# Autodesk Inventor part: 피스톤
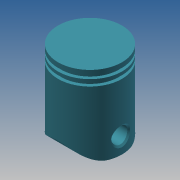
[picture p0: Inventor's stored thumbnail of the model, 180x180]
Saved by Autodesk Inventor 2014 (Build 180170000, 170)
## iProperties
Created: 2017-05
Part Number: 피스톤
Material: 알루미늄 6061
Document SubType Name: Modeling
Designer: mduedu
Density: 2.71 g/cm^3
Mass: 87.6985 g
Surface Area: 150.47 cm^2
Volume: 32.3611 cm^3
Appearance: 커뎃 파란색
Author: mduedu
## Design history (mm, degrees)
sketch "스케치1"
  geometry: L1 (0, 0)-(20, 0); L2 (20, -50)-(15, -50); L3 (15, -50)-(15, -5); L4 (15, -5)-(0, -5); L5 (0, -5)-(0, 0); L6 (20, -3)-(18, -3); L7 (18, -3)-(18, -5); L8 (18, -5)-(20, -5); L9 (20, -7)-(18, -7); L10 (18, -7)-(18, -9); L11 (18, -9)-(20, -9); L12 (20, 0)-(20, -3); L13 (20, -5)-(20, -7); L14 (20, -9)-(20, -50); L15 (0, -60)-(0, 10) reference
  constraints: 28 end point, 10 parallel, 5 perpendicular, 4 collinear, 3 horizontal
  dimensions: "d0" = 20 distance of L1.start L1.end; "d1" = 2 distance of L6.start L6.end; "d2" = 2 distance of L6.end L7.end; "d3" = 2 distance of L8.end L9.start; "d4" = 3 distance of L1.end L6.start; "d5" = 5 distance of L2.start L2.end; "d6" = 50 distance between parallel lines of L1 L2; "d7" = 5 distance of L4.end L1.start
revolve "회전1" sketch "스케치1" stored, may be unused: angle "d8" = 90 deg
fillet "모깎기1" dims "d9" = 1
sketch "스케치2"
  geometry: L1 (-50, 15)-(-50, -15) reference; C1 r 10 at (-40, 0); 1 further point
  constraints: 1 centre point, 1 horizontal alignment
  dimensions: "d10" = 20 diameter of C1; "d11" = 10 distance from line of C1.centre L1
extrude "돌출1" join sketch "스케치2" stored distance "d12" = 10; taper "d13" = 0 deg
sketch "스케치3"
  geometry: L1 (0, -20)-(-3, -20) reference; L2 (-3, -20)-(-3, -18) reference; L3 (-3, -18)-(-5, -18) reference; L4 (-5, -18)-(-5, -20) reference; L5 (-5, -20)-(-7, -20) reference; L6 (-7, -20)-(-7, -18) reference; L7 (-7, -18)-(-9, -18) reference; L8 (-9, -18)-(-9, -20) reference; L9 (-9, -20)-(-50, -20) reference; L10 (-50, -20)-(-50, -15) reference; L11 (-50, -15)-(-6, -15) reference; L12 (-5, -14)-(-5, 14) reference; L13 (-6, 15)-(-50, 15) reference; L14 (-50, 15)-(-50, 20) reference; L15 (-50, 20)-(-9, 20) reference; L16 (-9, 20)-(-9, 18) reference; L17 (-9, 18)-(-7, 18) reference; L18 (-7, 18)-(-7, 20) reference; L19 (-7, 20)-(-5, 20) reference; L20 (-5, 20)-(-5, 18) reference; L21 (-5, 18)-(-3, 18) reference; L22 (-3, 18)-(-3, 20) reference; L23 (-3, 20)-(0, 20) reference; L24 (0, 20)-(0, -20) reference; C1 r 10 at (-40, 0) reference; C2 r 5 at (-40, 0); A1 r 1 centre (-6, -14) between (-6, -15) and (-5, -14) reference; A2 r 1 centre (-6, 14) between (-5, 14) and (-6, 15) reference; 1 further point
  constraints: 1 centre point, 1 coincident
  dimensions: "d15" = 10 diameter of C2
extrude "돌출2" cut sketch "스케치3" stored distance "d16" = 10; taper "d17" = 0 deg
sketch "스케치4"
  geometry: L1 (15, -50)-(-15, -50) reference; L2 (-15, -50)-(-20, -50) reference; L3 (-20, -50)-(-20, -45) reference; L4 (20, -45)-(20, -50) reference; L5 (20, -50)-(15, -50) reference; L6 (-15, -30)-(15, -30) reference; L7 (15, -30)-(15, -6) reference; L8 (14, -5)-(-14, -5) reference; L9 (-15, -6)-(-15, -30) reference; L10 (-20, -3)-(-20, 0) reference; L11 (-20, 0)-(20, 0) reference; L12 (20, 0)-(20, -3) reference; L13 (20, -3)-(18, -3) reference; L14 (18, -3)-(18, -5) reference; L15 (18, -5)-(20, -5) reference; L16 (20, -5)-(20, -7) reference; L17 (20, -7)-(18, -7) reference; L18 (18, -7)-(18, -9) reference; L19 (18, -9)-(20, -9) reference; L20 (-20, -9)-(-18, -9) reference; L21 (-18, -9)-(-18, -7) reference; L22 (-18, -7)-(-20, -7) reference; L23 (-20, -7)-(-20, -5) reference; L24 (-20, -5)-(-18, -5) reference; L25 (-18, -5)-(-18, -3) reference; L26 (-18, -3)-(-20, -3) reference; L27 (0, 0)-(0, -50); L28 (-5.698, -50)-(-5, -30); L29 (5.698, -50)-(5, -30); L30 (-5, -30)-(5, -30); L31 (-5.698, -50)-(5.698, -50); L32 (-20, -45)-(20, -45) reference; L33 (20, -9)-(20, -35) reference; L34 (20, -35)-(-20, -35) reference; L35 (-20, -35)-(-20, -9) reference; A1 r 1 centre (14, -6) between (15, -6) and (14, -5) reference; A2 r 1 centre (-14, -6) between (-14, -5) and (-15, -6) reference
  constraints: 10 end point, 2 point on line, 2 symmetric about line, 1 midpoint, 1 parallel, 1 perpendicular
  dimensions: "d18" = 2 deg angle of L27 L28; "d19" = 5 distance from line of L27 L28.end
extrude "돌출3" cut sketch "스케치4" stored distance "d20" = 20; taper "d21" = 0 deg
chamfer "모따기1" distance "d22" = 1; stored, may be unused: second distance "d23" = 2, angle "d24" = 45 deg
sketch "스케치5"
  geometry: L1 (-50, 0)-(-50, -15) reference; L2 (-50, 15)-(-50, 0) reference; L3 (-9, 20)-(-50, 20) reference; L4 (-50, 20)-(-50, -20) reference; L5 (-9, -20)-(-50, -20) reference; L6 (-42.483, -20)-(-50, -20); L7 (-50, -20)-(-50, -7); L8 (-42.483, 20)-(-50, 20); L9 (-50, 20)-(-50, 7); A1 r 15 centre (-35, 7) between (-42.483, 20) and (-50, 7); A2 r 15 centre (-35, -7) between (-42.483, -20) and (-50, -7); 1 further point
  constraints: 8 end point, 4 point on circle, 4 point on line, 2 centre point, 2 tangent, 1 collinear, 1 equal radius, 1 perpendicular
  dimensions: "d25" = 30 diameter of A1; "d26" = 7 vertical distance of A2.centre point (0, 0); "d27" = 7 vertical distance of point (0, 0) A1.centre (= d26)
extrude "돌출4" cut sketch "스케치5" stored distance "d28" = 20; taper "d29" = 0 deg
node "솔리드1"
node "절단 모서리 투영1"
node "절단 모서리 투영2"
